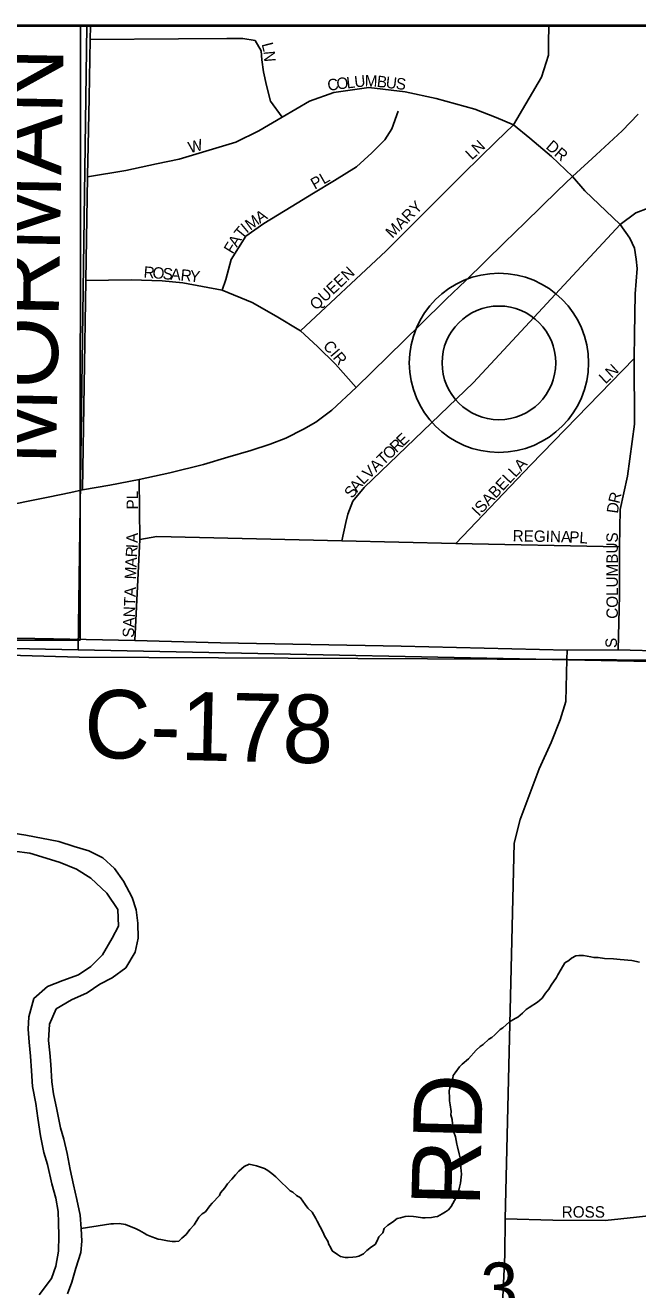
# Model space of a CAD drawing. Extents: x 0 to 34, y -2.3 to 22.
# Drawn here: x 5.622 to 6.13, y 19.85 to 20.9 of the extents above; entities that cross this region are included whole.
import ezdxf

# ---------------------------------------------------------------- set-up
doc = ezdxf.new("R2010")
doc.units = 0
for name, color, linetype in [('GM_X_City_Street', 7, 'Continuous'), ('GM_X_Corporation', 7, 'Continuous'), ('GM_X_County', 7, 'Continuous'), ('GM_X_County_Road', 7, 'Continuous'), ('GM_X_County_Road_Text', 7, 'Continuous'), ('GM_X_Major_River', 7, 'Continuous'), ('GM_X_Minor_River', 7, 'Continuous'), ('GM_X_Section', 7, 'Continuous'), ('GM_X_Section_Text', 7, 'Continuous'), ('GM_X_State_Route', 7, 'Continuous'), ('GM_X_Township', 7, 'Continuous'), ('GM_X_Township_Road', 7, 'Continuous'), ('GM_X_Township_Road_Text', 7, 'Continuous'), ('GM_X_Township_Subdivision', 7, 'Continuous'), ('GM_X_Township_Subdivision_Text', 7, 'Continuous'), ('GM_X_Unincorporated', 7, 'Continuous'), ('GM_X_Unincorporated_Location', 7, 'Continuous'), ('SH_Data', 7, 'Continuous')]:
    doc.layers.add(name, color=color, linetype=linetype)

msp = doc.modelspace()

# ---------------------------------------------------------------- linework, layer by layer
at = {"layer": 'GM_X_City_Street'}
for p, q in [((5.5986, 20.3911), (5.6453, 20.3903)), ((5.6453, 20.3903), (5.6723, 20.3897))]:
    msp.add_line(p, q, dxfattribs=at)
at = {"layer": 'GM_X_Corporation'}
for p, q in [((5.6676, 20.8994), (5.2773, 20.8994)), ((5.6675, 20.3893), (5.6676, 20.8994)), ((5.5312, 20.3894), (5.6675, 20.3893))]:
    msp.add_line(p, q, dxfattribs=at)
at = {"layer": 'GM_X_County'}
msp.add_line((8.8792, 20.8994), (2.0792, 20.8994), dxfattribs=at)
at = {"layer": 'GM_X_County_Road'}
for p, q in [((5.6757, 20.8881), (5.6761, 20.8994)), ((5.6749, 20.8399), (5.6757, 20.8881)), ((5.674, 20.7998), (5.6749, 20.8399)), ((5.6734, 20.7752), (5.674, 20.7998)), ((5.6734, 20.7742), (5.6734, 20.7752)), ((5.6721, 20.6881), (5.6734, 20.7742)), ((5.6692, 20.514), (5.6721, 20.6881)), ((5.6723, 20.3897), (5.7127, 20.3889)), ((5.7127, 20.3889), (5.7839, 20.387)), ((5.7839, 20.387), (5.9339, 20.3842)), ((5.9339, 20.3842), (6.0716, 20.381)), ((6.0716, 20.381), (6.1141, 20.3811)), ((6.1141, 20.3811), (6.2758, 20.377))]:
    msp.add_line(p, q, dxfattribs=at)
at = {"layer": 'GM_X_Major_River'}
for p, q in [((5.6224, 20.2272), (5.6118, 20.229)), ((5.6496, 20.2221), (5.6224, 20.2272)), ((5.6625, 20.218), (5.6496, 20.2221)), ((5.6745, 20.2144), (5.6625, 20.218)), ((5.6126, 20.2141), (5.6255, 20.2123)), ((5.6255, 20.2123), (5.6391, 20.2083)), ((5.6391, 20.2083), (5.6508, 20.2046)), ((5.6862, 20.2084), (5.6745, 20.2144)), ((5.6959, 20.1995), (5.6862, 20.2084)), ((5.6508, 20.2046), (5.6643, 20.199)), ((5.6643, 20.199), (5.6763, 20.1915)), ((5.7033, 20.1891), (5.6959, 20.1995)), ((5.6763, 20.1915), (5.6894, 20.1791)), ((5.7106, 20.1756), (5.7033, 20.1891)), ((5.6894, 20.1791), (5.6986, 20.1656)), ((5.6986, 20.1656), (5.6991, 20.1516)), ((5.7138, 20.1653), (5.7106, 20.1756)), ((5.7154, 20.1543), (5.7138, 20.1653)), ((5.6991, 20.1516), (5.6939, 20.1418)), ((5.7156, 20.1417), (5.7154, 20.1543)), ((5.6939, 20.1418), (5.686, 20.1279)), ((5.713, 20.13), (5.7156, 20.1417)), ((5.686, 20.1279), (5.6763, 20.1182)), ((5.7052, 20.1172), (5.713, 20.13)), ((5.6763, 20.1182), (5.6659, 20.1112)), ((5.694, 20.1087), (5.7052, 20.1172)), ((5.6529, 20.1065), (5.6402, 20.1015)), ((5.6659, 20.1112), (5.6529, 20.1065)), ((5.6732, 20.0963), (5.6836, 20.1036)), ((5.6836, 20.1036), (5.694, 20.1087)), ((5.6402, 20.1015), (5.629, 20.0915)), ((5.6601, 20.0904), (5.6732, 20.0963)), ((5.629, 20.0915), (5.6249, 20.0763)), ((5.6419, 20.0703), (5.6474, 20.0831)), ((5.6474, 20.0831), (5.6601, 20.0904)), ((5.6249, 20.0763), (5.6243, 20.0661)), ((5.6243, 20.0661), (5.6252, 20.0554)), ((5.6412, 20.0566), (5.6419, 20.0703)), ((5.6252, 20.0554), (5.6261, 20.0437)), ((5.6421, 20.0464), (5.6412, 20.0566)), ((5.6261, 20.0437), (5.627, 20.0315)), ((5.6431, 20.0368), (5.6421, 20.0464)), ((5.627, 20.0315), (5.6278, 20.0185)), ((5.6439, 20.0224), (5.6431, 20.0368)), ((5.6278, 20.0185), (5.6306, 20.0044)), ((5.6452, 20.0125), (5.6439, 20.0224)), ((5.648, 19.9995), (5.6452, 20.0125)), ((5.6306, 20.0044), (5.6322, 19.9922)), ((5.6511, 19.9843), (5.648, 19.9995)), ((5.6322, 19.9922), (5.6346, 19.9774)), ((5.6346, 19.9774), (5.6373, 19.9636)), ((5.6539, 19.9747), (5.6511, 19.9843)), ((5.6567, 19.9629), (5.6539, 19.9747)), ((5.6373, 19.9636), (5.6402, 19.9537)), ((5.6591, 19.9495), (5.6567, 19.9629)), ((5.6402, 19.9537), (5.644, 19.9377)), ((5.6619, 19.9369), (5.6591, 19.9495)), ((5.644, 19.9377), (5.6472, 19.9258)), ((5.6646, 19.9247), (5.6619, 19.9369)), ((5.6472, 19.9258), (5.6492, 19.9148)), ((5.6674, 19.9117), (5.6646, 19.9247)), ((5.6492, 19.9148), (5.6494, 19.9053)), ((5.6494, 19.9053), (5.6496, 19.8946)), ((5.6683, 19.9007), (5.6674, 19.9117)), ((5.6496, 19.8946), (5.6493, 19.8817)), ((5.6688, 19.8901), (5.6683, 19.9007)), ((5.6679, 19.8806), (5.6688, 19.8901)), ((5.6493, 19.8817), (5.6471, 19.8692)), ((5.6638, 19.8677), (5.6679, 19.8806)), ((5.6471, 19.8692), (5.6435, 19.859)), ((5.6605, 19.856), (5.6638, 19.8677)), ((5.6435, 19.859), (5.6333, 19.8456)), ((5.6569, 19.8462), (5.6605, 19.856))]:
    msp.add_line(p, q, dxfattribs=at)
at = {"layer": 'GM_X_Minor_River'}
for p, q in [((6.0729, 20.1233), (6.0752, 20.1251)), ((6.0752, 20.1251), (6.0787, 20.127)), ((6.0787, 20.127), (6.0813, 20.1273)), ((6.0813, 20.1273), (6.0851, 20.1272)), ((6.0851, 20.1272), (6.0912, 20.1263)), ((6.0912, 20.1263), (6.0938, 20.1258)), ((6.0938, 20.1258), (6.0973, 20.1257)), ((6.0973, 20.1257), (6.1026, 20.1248)), ((6.1026, 20.1248), (6.1102, 20.1246)), ((6.1102, 20.1246), (6.1155, 20.1241)), ((6.1155, 20.1241), (6.1253, 20.1231)), ((6.0638, 20.1114), (6.0666, 20.1159)), ((6.0666, 20.1159), (6.0698, 20.1211)), ((6.0698, 20.1211), (6.0729, 20.1233)), ((6.1253, 20.1231), (6.1318, 20.1218)), ((6.0563, 20.0994), (6.0583, 20.1028)), ((6.0583, 20.1028), (6.0627, 20.1091)), ((6.0627, 20.1091), (6.0638, 20.1114)), ((6.047, 20.0886), (6.0508, 20.0919)), ((6.0508, 20.0919), (6.0536, 20.096)), ((6.0536, 20.096), (6.0563, 20.0994)), ((6.0346, 20.0794), (6.0377, 20.0824)), ((6.0377, 20.0824), (6.04, 20.0842)), ((6.04, 20.0842), (6.047, 20.0886)), ((6.0183, 20.0673), (6.0238, 20.0721)), ((6.0238, 20.0721), (6.0284, 20.075)), ((6.0284, 20.075), (6.0307, 20.0761)), ((6.0307, 20.0761), (6.0346, 20.0794)), ((6.009, 20.0592), (6.0117, 20.0614)), ((6.0117, 20.0614), (6.016, 20.0658)), ((6.016, 20.0658), (6.0183, 20.0673)), ((5.9962, 20.0488), (5.9993, 20.0518)), ((5.9993, 20.0518), (6.002, 20.0533)), ((6.002, 20.0533), (6.0067, 20.0577)), ((6.0067, 20.0577), (6.009, 20.0592)), ((5.9845, 20.037), (5.9896, 20.0414)), ((5.9896, 20.0414), (5.9962, 20.0488)), ((5.9771, 20.0277), (5.9787, 20.0299)), ((5.9787, 20.0299), (5.9822, 20.0348)), ((5.9822, 20.0348), (5.9845, 20.037)), ((5.9742, 20.0175), (5.9755, 20.0228)), ((5.9755, 20.0228), (5.9767, 20.0254)), ((5.9767, 20.0254), (5.9771, 20.0277)), ((5.9738, 20.0148), (5.9742, 20.0175)), ((5.974, 20.0088), (5.9738, 20.0148)), ((5.9739, 20.0065), (5.974, 20.0088)), ((5.9746, 20.0034), (5.9739, 20.0065)), ((5.9753, 19.9977), (5.9746, 20.0034)), ((5.9752, 19.9951), (5.9753, 19.9977)), ((5.9763, 19.9912), (5.9752, 19.9951)), ((5.9768, 19.9836), (5.9763, 19.9912)), ((5.9775, 19.9806), (5.9768, 19.9836)), ((5.979, 19.9767), (5.9775, 19.9806)), ((5.98, 19.9706), (5.979, 19.9767)), ((5.9807, 19.9683), (5.98, 19.9706)), ((5.9821, 19.9626), (5.9807, 19.9683)), ((5.9827, 19.9592), (5.9821, 19.9626)), ((5.9834, 19.9546), (5.9827, 19.9592)), ((5.7933, 19.9415), (5.7964, 19.9452)), ((5.7964, 19.9452), (5.7992, 19.9482)), ((5.7992, 19.9482), (5.8035, 19.9522)), ((5.8035, 19.9522), (5.8077, 19.954)), ((5.8077, 19.954), (5.8137, 19.9527)), ((5.8137, 19.9527), (5.8205, 19.9503)), ((5.8205, 19.9503), (5.8231, 19.9487)), ((5.8231, 19.9487), (5.8265, 19.9463)), ((5.8265, 19.9463), (5.8299, 19.9436)), ((5.983, 19.9383), (5.9839, 19.9458)), ((5.9833, 19.9512), (5.9834, 19.9546)), ((5.9839, 19.9458), (5.9833, 19.9512)), ((5.7839, 19.9303), (5.7874, 19.9344)), ((5.7874, 19.9344), (5.7898, 19.9378)), ((5.7898, 19.9378), (5.7933, 19.9415)), ((5.8299, 19.9436), (5.8336, 19.9397)), ((5.8336, 19.9397), (5.8395, 19.9342)), ((5.9809, 19.9284), (5.9822, 19.9349)), ((5.9822, 19.9349), (5.983, 19.9383)), ((5.7769, 19.9217), (5.7831, 19.928)), ((5.7831, 19.928), (5.7839, 19.9303)), ((5.8395, 19.9342), (5.8418, 19.9319)), ((5.8418, 19.9319), (5.844, 19.9307)), ((5.844, 19.9307), (5.847, 19.928)), ((5.847, 19.928), (5.8504, 19.926)), ((5.8504, 19.926), (5.8541, 19.9206)), ((5.9753, 19.9187), (5.9781, 19.9239)), ((5.9781, 19.9239), (5.9809, 19.9284)), ((5.7687, 19.9128), (5.7714, 19.9143)), ((5.7714, 19.9143), (5.7749, 19.9195)), ((5.7749, 19.9195), (5.7769, 19.9217)), ((5.8541, 19.9206), (5.8563, 19.9175)), ((5.8563, 19.9175), (5.86, 19.914)), ((5.86, 19.914), (5.8629, 19.909)), ((5.968, 19.9128), (5.9707, 19.9143)), ((5.9707, 19.9143), (5.973, 19.9161)), ((5.973, 19.9161), (5.9753, 19.9187)), ((5.6683, 19.9007), (5.6875, 19.9035)), ((5.6875, 19.9035), (5.6928, 19.9045)), ((5.6928, 19.9045), (5.6951, 19.9044)), ((5.6951, 19.9044), (5.6997, 19.9047)), ((5.6997, 19.9047), (5.705, 19.9038)), ((5.705, 19.9038), (5.7084, 19.9026)), ((5.7585, 19.8998), (5.762, 19.9035)), ((5.762, 19.9035), (5.766, 19.9099)), ((5.766, 19.9099), (5.7687, 19.9128)), ((5.8629, 19.909), (5.864, 19.9067)), ((5.864, 19.9067), (5.8666, 19.902)), ((5.9198, 19.9007), (5.9229, 19.9033)), ((5.9229, 19.9033), (5.9267, 19.9058)), ((5.9267, 19.9058), (5.9306, 19.9088)), ((5.9306, 19.9088), (5.9333, 19.9095)), ((5.9333, 19.9095), (5.9371, 19.9105)), ((5.9371, 19.9105), (5.9398, 19.9108)), ((5.9398, 19.9108), (5.944, 19.9104)), ((5.944, 19.9104), (5.9462, 19.9103)), ((5.9462, 19.9103), (5.9515, 19.9094)), ((5.9515, 19.9094), (5.9538, 19.9094)), ((5.9538, 19.9094), (5.9591, 19.9096)), ((5.9591, 19.9096), (5.9618, 19.9103)), ((5.9618, 19.9103), (5.9641, 19.9106)), ((5.9641, 19.9106), (5.968, 19.9128)), ((5.7084, 19.9026), (5.7133, 19.9005)), ((5.7133, 19.9005), (5.7167, 19.8989)), ((5.7167, 19.8989), (5.7204, 19.8966)), ((5.7204, 19.8966), (5.7227, 19.8954)), ((5.7227, 19.8954), (5.7268, 19.8937)), ((5.7268, 19.8937), (5.7298, 19.8925)), ((5.7298, 19.8925), (5.7321, 19.8917)), ((5.7492, 19.8901), (5.7519, 19.8924)), ((5.7519, 19.8924), (5.7554, 19.8957)), ((5.7554, 19.8957), (5.7585, 19.8998)), ((5.8666, 19.902), (5.8687, 19.8978)), ((5.8687, 19.8978), (5.8706, 19.894)), ((5.8706, 19.894), (5.8731, 19.8901)), ((5.9138, 19.8902), (5.9154, 19.8936)), ((5.9154, 19.8936), (5.9185, 19.8969)), ((5.9185, 19.8969), (5.9198, 19.9007)), ((5.7321, 19.8917), (5.7343, 19.8913)), ((5.7343, 19.8913), (5.737, 19.8908)), ((5.737, 19.8908), (5.74, 19.8904)), ((5.74, 19.8904), (5.7438, 19.8899)), ((5.7438, 19.8899), (5.7465, 19.8898)), ((5.7465, 19.8898), (5.7492, 19.8901)), ((5.8731, 19.8901), (5.8738, 19.8874)), ((5.8738, 19.8874), (5.8753, 19.8851)), ((5.8753, 19.8851), (5.8767, 19.882)), ((5.8767, 19.882), (5.8809, 19.8789)), ((5.9025, 19.8795), (5.9053, 19.8824)), ((5.9053, 19.8824), (5.9091, 19.8854)), ((5.9091, 19.8854), (5.9122, 19.8872)), ((5.9122, 19.8872), (5.9138, 19.8902)), ((5.8809, 19.8789), (5.8835, 19.8773)), ((5.8835, 19.8773), (5.8873, 19.8764)), ((5.8873, 19.8764), (5.8899, 19.8764)), ((5.8899, 19.8764), (5.8937, 19.8767)), ((5.8937, 19.8767), (5.8964, 19.877)), ((5.8964, 19.877), (5.8987, 19.8777)), ((5.8987, 19.8777), (5.9025, 19.8795))]:
    msp.add_line(p, q, dxfattribs=at)
at = {"layer": 'GM_X_Section'}
for p, q in [((5.6728, 20.8994), (4.6838, 20.8994)), ((5.6658, 20.3811), (5.6728, 20.8994)), ((5.6728, 20.8994), (5.6658, 20.3811)), ((6.6703, 20.8994), (5.6728, 20.8994)), ((5.4223, 20.3866), (5.6658, 20.3811)), ((5.4223, 20.3866), (5.6658, 20.3811)), ((5.6658, 20.3811), (6.6408, 20.3616)), ((5.6658, 20.3811), (6.6408, 20.3616))]:
    msp.add_line(p, q, dxfattribs=at)
at = {"layer": 'GM_X_State_Route'}
for p, q in [((6.1172, 20.8124), (6.1307, 20.8263)), ((6.0957, 20.7923), (6.1172, 20.8124)), ((6.076, 20.7744), (6.0957, 20.7923)), ((6.0637, 20.7626), (6.076, 20.7744)), ((6.0367, 20.7362), (6.0637, 20.7626)), ((6.0196, 20.7196), (6.0367, 20.7362)), ((5.9875, 20.6881), (6.0196, 20.7196)), ((5.9712, 20.6725), (5.9875, 20.6881)), ((5.9495, 20.6511), (5.9712, 20.6725)), ((5.923, 20.6251), (5.9495, 20.6511)), ((5.8966, 20.599), (5.923, 20.6251)), ((5.8763, 20.5802), (5.8966, 20.599)), ((5.8631, 20.5702), (5.8763, 20.5802)), ((5.8529, 20.5645), (5.8631, 20.5702)), ((5.8252, 20.5521), (5.838, 20.557)), ((5.838, 20.557), (5.8529, 20.5645)), ((5.79, 20.5412), (5.809, 20.5468)), ((5.809, 20.5468), (5.8252, 20.5521)), ((5.7418, 20.5282), (5.7698, 20.5353)), ((5.7698, 20.5353), (5.79, 20.5412)), ((5.6921, 20.5179), (5.7163, 20.5226)), ((5.7163, 20.5226), (5.7418, 20.5282)), ((5.6409, 20.5081), (5.6596, 20.512)), ((5.6596, 20.512), (5.6692, 20.514)), ((5.6692, 20.514), (5.6921, 20.5179)), ((5.5931, 20.4984), (5.6409, 20.5081))]:
    msp.add_line(p, q, dxfattribs=at)
at = {"layer": 'GM_X_Township'}
for p, q in [((8.674, 20.8994), (2.6175, 20.8994)), ((5.3946, 20.3826), (5.6667, 20.3752)), ((5.3946, 20.3826), (5.6667, 20.3752)), ((5.6667, 20.3752), (6.0714, 20.3731)), ((5.6667, 20.3752), (6.0714, 20.3731)), ((6.0714, 20.3731), (6.8005, 20.3694)), ((6.0714, 20.3731), (6.8005, 20.3694))]:
    msp.add_line(p, q, dxfattribs=at)
at = {"layer": 'GM_X_Township_Road'}
for p, q in [((6.0714, 20.3731), (6.0716, 20.381)), ((6.0705, 20.3383), (6.0714, 20.3731)), ((6.0659, 20.3231), (6.0705, 20.3383)), ((6.0584, 20.3043), (6.0659, 20.3231)), ((6.0485, 20.2823), (6.0584, 20.3043)), ((6.0325, 20.2402), (6.0485, 20.2823)), ((6.0277, 20.2205), (6.0325, 20.2402)), ((6.0202, 19.9087), (6.0277, 20.2205)), ((6.02, 19.8787), (6.0202, 19.9087)), ((6.0158, 19.7946), (6.02, 19.8787))]:
    msp.add_line(p, q, dxfattribs=at)
at = {"layer": 'GM_X_Township_Subdivision'}
for p, q in [((6.0562, 20.8857), (6.0563, 20.8994)), ((5.6757, 20.8881), (5.7491, 20.8887)), ((5.7491, 20.8887), (5.7891, 20.8889)), ((5.7891, 20.8889), (5.8024, 20.8889)), ((5.8024, 20.8889), (5.8126, 20.8875)), ((5.8126, 20.8875), (5.8177, 20.8789)), ((6.0561, 20.8753), (6.0562, 20.8857)), ((5.8177, 20.8789), (5.8183, 20.8714)), ((5.8183, 20.8714), (5.8195, 20.8614)), ((6.0503, 20.8568), (6.0561, 20.8753)), ((5.8195, 20.8614), (5.8222, 20.8499)), ((5.8222, 20.8499), (5.8255, 20.8369)), ((5.907, 20.8482), (5.878, 20.8442)), ((5.9373, 20.8448), (5.907, 20.8482)), ((6.0271, 20.8173), (6.0503, 20.8568)), ((5.878, 20.8442), (5.8578, 20.8371)), ((5.9629, 20.8391), (5.9373, 20.8448)), ((5.9949, 20.8303), (5.9629, 20.8391)), ((5.8255, 20.8369), (5.835, 20.8237)), ((5.8578, 20.8371), (5.835, 20.8237)), ((5.9314, 20.8286), (5.9262, 20.8139)), ((6.0128, 20.8233), (5.9949, 20.8303)), ((5.835, 20.8237), (5.8158, 20.8122)), ((6.0271, 20.8173), (6.0128, 20.8233)), ((6.0128, 20.8035), (6.0271, 20.8173)), ((6.0407, 20.8062), (6.0271, 20.8173)), ((5.8158, 20.8122), (5.7966, 20.8028)), ((5.9262, 20.8139), (5.9202, 20.8048)), ((6.0586, 20.7909), (6.0407, 20.8062)), ((5.7966, 20.8028), (5.7495, 20.7887)), ((5.9202, 20.8048), (5.9094, 20.7941)), ((5.9857, 20.777), (6.0128, 20.8035)), ((5.7495, 20.7887), (5.7307, 20.7849)), ((5.9094, 20.7941), (5.8968, 20.7823)), ((6.076, 20.7744), (6.0586, 20.7909)), ((5.7054, 20.7794), (5.6734, 20.7742)), ((5.7307, 20.7849), (5.7054, 20.7794)), ((5.8968, 20.7823), (5.8785, 20.771)), ((5.9213, 20.7126), (5.9857, 20.777)), ((5.8785, 20.771), (5.8612, 20.7606)), ((6.0863, 20.7625), (6.076, 20.7744)), ((5.8612, 20.7606), (5.8425, 20.7493)), ((6.1155, 20.7344), (6.0863, 20.7625)), ((5.8425, 20.7493), (5.8199, 20.7354)), ((6.1286, 20.7442), (6.1155, 20.7344)), ((6.1388, 20.748), (6.1286, 20.7442)), ((5.8199, 20.7354), (5.8049, 20.7248)), ((6.1155, 20.7344), (5.9938, 20.6033)), ((6.1237, 20.7233), (6.1155, 20.7344)), ((5.8049, 20.7248), (5.7926, 20.7054)), ((6.1275, 20.715), (6.1237, 20.7233)), ((5.8502, 20.6462), (5.9213, 20.7126)), ((6.129, 20.7056), (6.1275, 20.715)), ((5.7926, 20.7054), (5.7883, 20.6889)), ((6.1296, 20.6979), (6.129, 20.7056)), ((6.1281, 20.6768), (6.1296, 20.6979)), ((5.7098, 20.6885), (5.6721, 20.6881)), ((5.7355, 20.6878), (5.7098, 20.6885)), ((5.7526, 20.686), (5.7355, 20.6878)), ((5.7853, 20.6801), (5.7526, 20.686)), ((5.7883, 20.6889), (5.7853, 20.6801)), ((5.8103, 20.6696), (5.7853, 20.6801)), ((5.8301, 20.6585), (5.8103, 20.6696)), ((6.1275, 20.6431), (6.1281, 20.6768)), ((5.8502, 20.6462), (5.8301, 20.6585)), ((5.8644, 20.6333), (5.8502, 20.6462)), ((6.1273, 20.6231), (6.1275, 20.6431)), ((5.8793, 20.6186), (5.8644, 20.6333)), ((5.8966, 20.599), (5.8793, 20.6186)), ((6.1273, 20.6231), (6.0415, 20.5348)), ((6.1275, 20.5687), (6.1273, 20.6231)), ((5.9938, 20.6033), (5.9032, 20.516)), ((6.1218, 20.5254), (6.1275, 20.5687)), ((6.0415, 20.5348), (5.9793, 20.4696)), ((5.7168, 20.4729), (5.7163, 20.5226)), ((6.1155, 20.4978), (6.1218, 20.5254)), ((5.9032, 20.516), (5.8938, 20.5047)), ((5.8938, 20.5047), (5.8896, 20.494)), ((5.8896, 20.494), (5.8879, 20.487)), ((6.1151, 20.4668), (6.1155, 20.4978)), ((5.8879, 20.487), (5.8847, 20.4717)), ((5.7127, 20.3889), (5.7168, 20.4729)), ((5.7311, 20.4754), (5.7168, 20.4729)), ((5.8847, 20.4717), (5.7311, 20.4754)), ((5.9793, 20.4696), (5.8847, 20.4717)), ((6.1151, 20.4668), (5.9793, 20.4696)), ((6.1151, 20.4267), (6.1151, 20.4668)), ((6.1141, 20.3811), (6.1151, 20.4267)), ((6.0202, 19.9087), (6.0596, 19.9075)), ((6.0596, 19.9075), (6.1032, 19.9072)), ((6.1032, 19.9072), (6.1293, 19.9099)), ((6.1293, 19.9099), (6.1559, 19.9131))]:
    msp.add_line(p, q, dxfattribs=at)
at = {"layer": 'GM_X_Unincorporated'}
for radius in [0.0744, 0.0472]:
    msp.add_circle((6.015, 20.6196), radius, dxfattribs=at)
at = {"layer": 'GM_X_Unincorporated_Location'}
msp.add_line((6.015, 20.6196), (6.015, 20.6196), dxfattribs=at)
at = {"layer": 'SH_Data'}
msp.add_line((2.1, 20.9), (8.9, 20.9), dxfattribs=at)

# ---------------------------------------------------------------- texts
at = {"layer": 'GM_X_County_Road_Text'}
for s, rotation, p in [('MORMAN', 88.9634, (5.6473, 20.5348)), ('C-178', 358.6238, (5.6701, 20.2917))]:
    msp.add_text(s, height=0.05682, rotation=rotation, dxfattribs=at).set_placement(p)
at = {"layer": 'GM_X_Section_Text'}
msp.add_text('3', height=0.0419, rotation=0, dxfattribs=at).set_placement((5.9996, 19.8304))
at = {"layer": 'GM_X_Township_Road_Text'}
msp.add_text('RD', height=0.05682, rotation=88.5189, dxfattribs=at).set_placement((5.999, 19.9184))
at = {"layer": 'GM_X_Township_Subdivision_Text'}
for s, rotation, p in [('L', 284.3675, (5.8179, 20.8844)), ('N', 274.9615, (5.8195, 20.8783)), ('M', 358.4334, (5.9035, 20.8492)), ('C', 9.0231, (5.8734, 20.8454)), ('O', 6.7692, (5.8807, 20.8466)), ('L', 6.3515, (5.8889, 20.8475)), ('U', 6.3517, (5.8955, 20.8483)), ('B', 353.7704, (5.9133, 20.8489)), ('U', 353.6043, (5.9207, 20.8481)), ('S', 353.291, (5.929, 20.8472)), ('W', 14.0459, (5.7584, 20.7937)), ('LN', 42.8801, (5.9925, 20.7876)), ('DR', 319.0844, (6.0533, 20.7983)), ('PL', 29.7432, (5.8621, 20.7634)), ('MARY', 44.9993, (5.9265, 20.7226)), ('A', 33.4779, (5.8166, 20.7351)), ('T', 50.9273, (5.8017, 20.7219)), ('I', 39.8, (5.8056, 20.7268)), ('M', 35.9818, (5.8086, 20.7293)), ('A', 58.2395, (5.7975, 20.7151)), ('F', 58.235, (5.794, 20.7094)), ('R', 355.6977, (5.7198, 20.6904)), ('O', 355.6901, (5.7272, 20.6899)), ('S', 355.6958, (5.7356, 20.6892)), ('A', 355.6243, (5.7422, 20.6888)), ('R', 354.0151, (5.7504, 20.6881)), ('Y', 352.9224, (5.7579, 20.6873)), ('QUEEN', 43.2619, (5.8633, 20.6627)), ('CIR', 310.4271, (5.8684, 20.6333)), ('LN', 42.8801, (6.1034, 20.6016)), ('R', 43.8124, (5.9299, 20.5445)), ('E', 43.8212, (5.9353, 20.5497)), ('T', 43.8212, (5.9191, 20.5341)), ('O', 43.7943, (5.9239, 20.5387)), ('V', 43.8447, (5.9071, 20.5226)), ('A', 43.7943, (5.9131, 20.5283)), ('ISABELLA', 46.8089, (5.9983, 20.4916)), ('L', 45.1159, (5.9024, 20.5179)), ('PL', 90, (5.7154, 20.4978)), ('S', 52.234, (5.8932, 20.5064)), ('A', 50.4365, (5.8973, 20.5116)), ('R', 76.5822, (6.1148, 20.5022)), ('D', 81.8583, (6.1137, 20.4941)), ('REGINA', 358.8947, (6.0263, 20.4713)), ('A', 88.8893, (5.7152, 20.4699)), ('PL', 356.4258, (6.0731, 20.4704)), ('COLUMBUS', 90, (6.1137, 20.407)), ('R', 87.1589, (5.7146, 20.4579)), ('I', 87.1816, (5.715, 20.4654)), ('M', 87.1621, (5.7137, 20.4396)), ('A', 87.1584, (5.7142, 20.4496)), ('SANTA', 87.5107, (5.712, 20.3912)), ('S', 90, (6.1129, 20.3828)), ('ROSS', 0, (6.0671, 19.9096))]:
    msp.add_text(s, height=0.00947, rotation=rotation, dxfattribs=at).set_placement(p)

doc.saveas('drawing.dxf')
